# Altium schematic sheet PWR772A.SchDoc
size 431 x 279 mm; Date: Not shown in title block; ApprovedBy: Not shown in title block; CheckedBy: Not shown in title block; Author: Not shown in title block; CompanyName: Not shown in title block; Engineer: Not shown in title block; Organization: Not shown in title block; Address1: Not shown in title block; Address2: Not shown in title block; Address3: Not shown in title block; Address4: Not shown in title block; DocumentNumber: 1; Revision: Use project parameter SCH_Rev; SheetNumber: 1; SheetTotal: 2; PageSetup: Record=PageOptions¦CenterHorizontal=True¦CenterVertical=True¦PrintScale=0.62¦XCorrection=1.00¦YCorrection=1.00¦PrintKind=0¦BorderSize=5000000¦LeftOffset=0¦BottomOffset=0¦Orientation=2¦PaperLength=1000¦PaperWidth=1000¦Scale=100¦PaperSource=15¦PrintQuality=600¦MediaType=1¦DitherType=10¦PrintScaleMode=1¦PaperKind=Letter
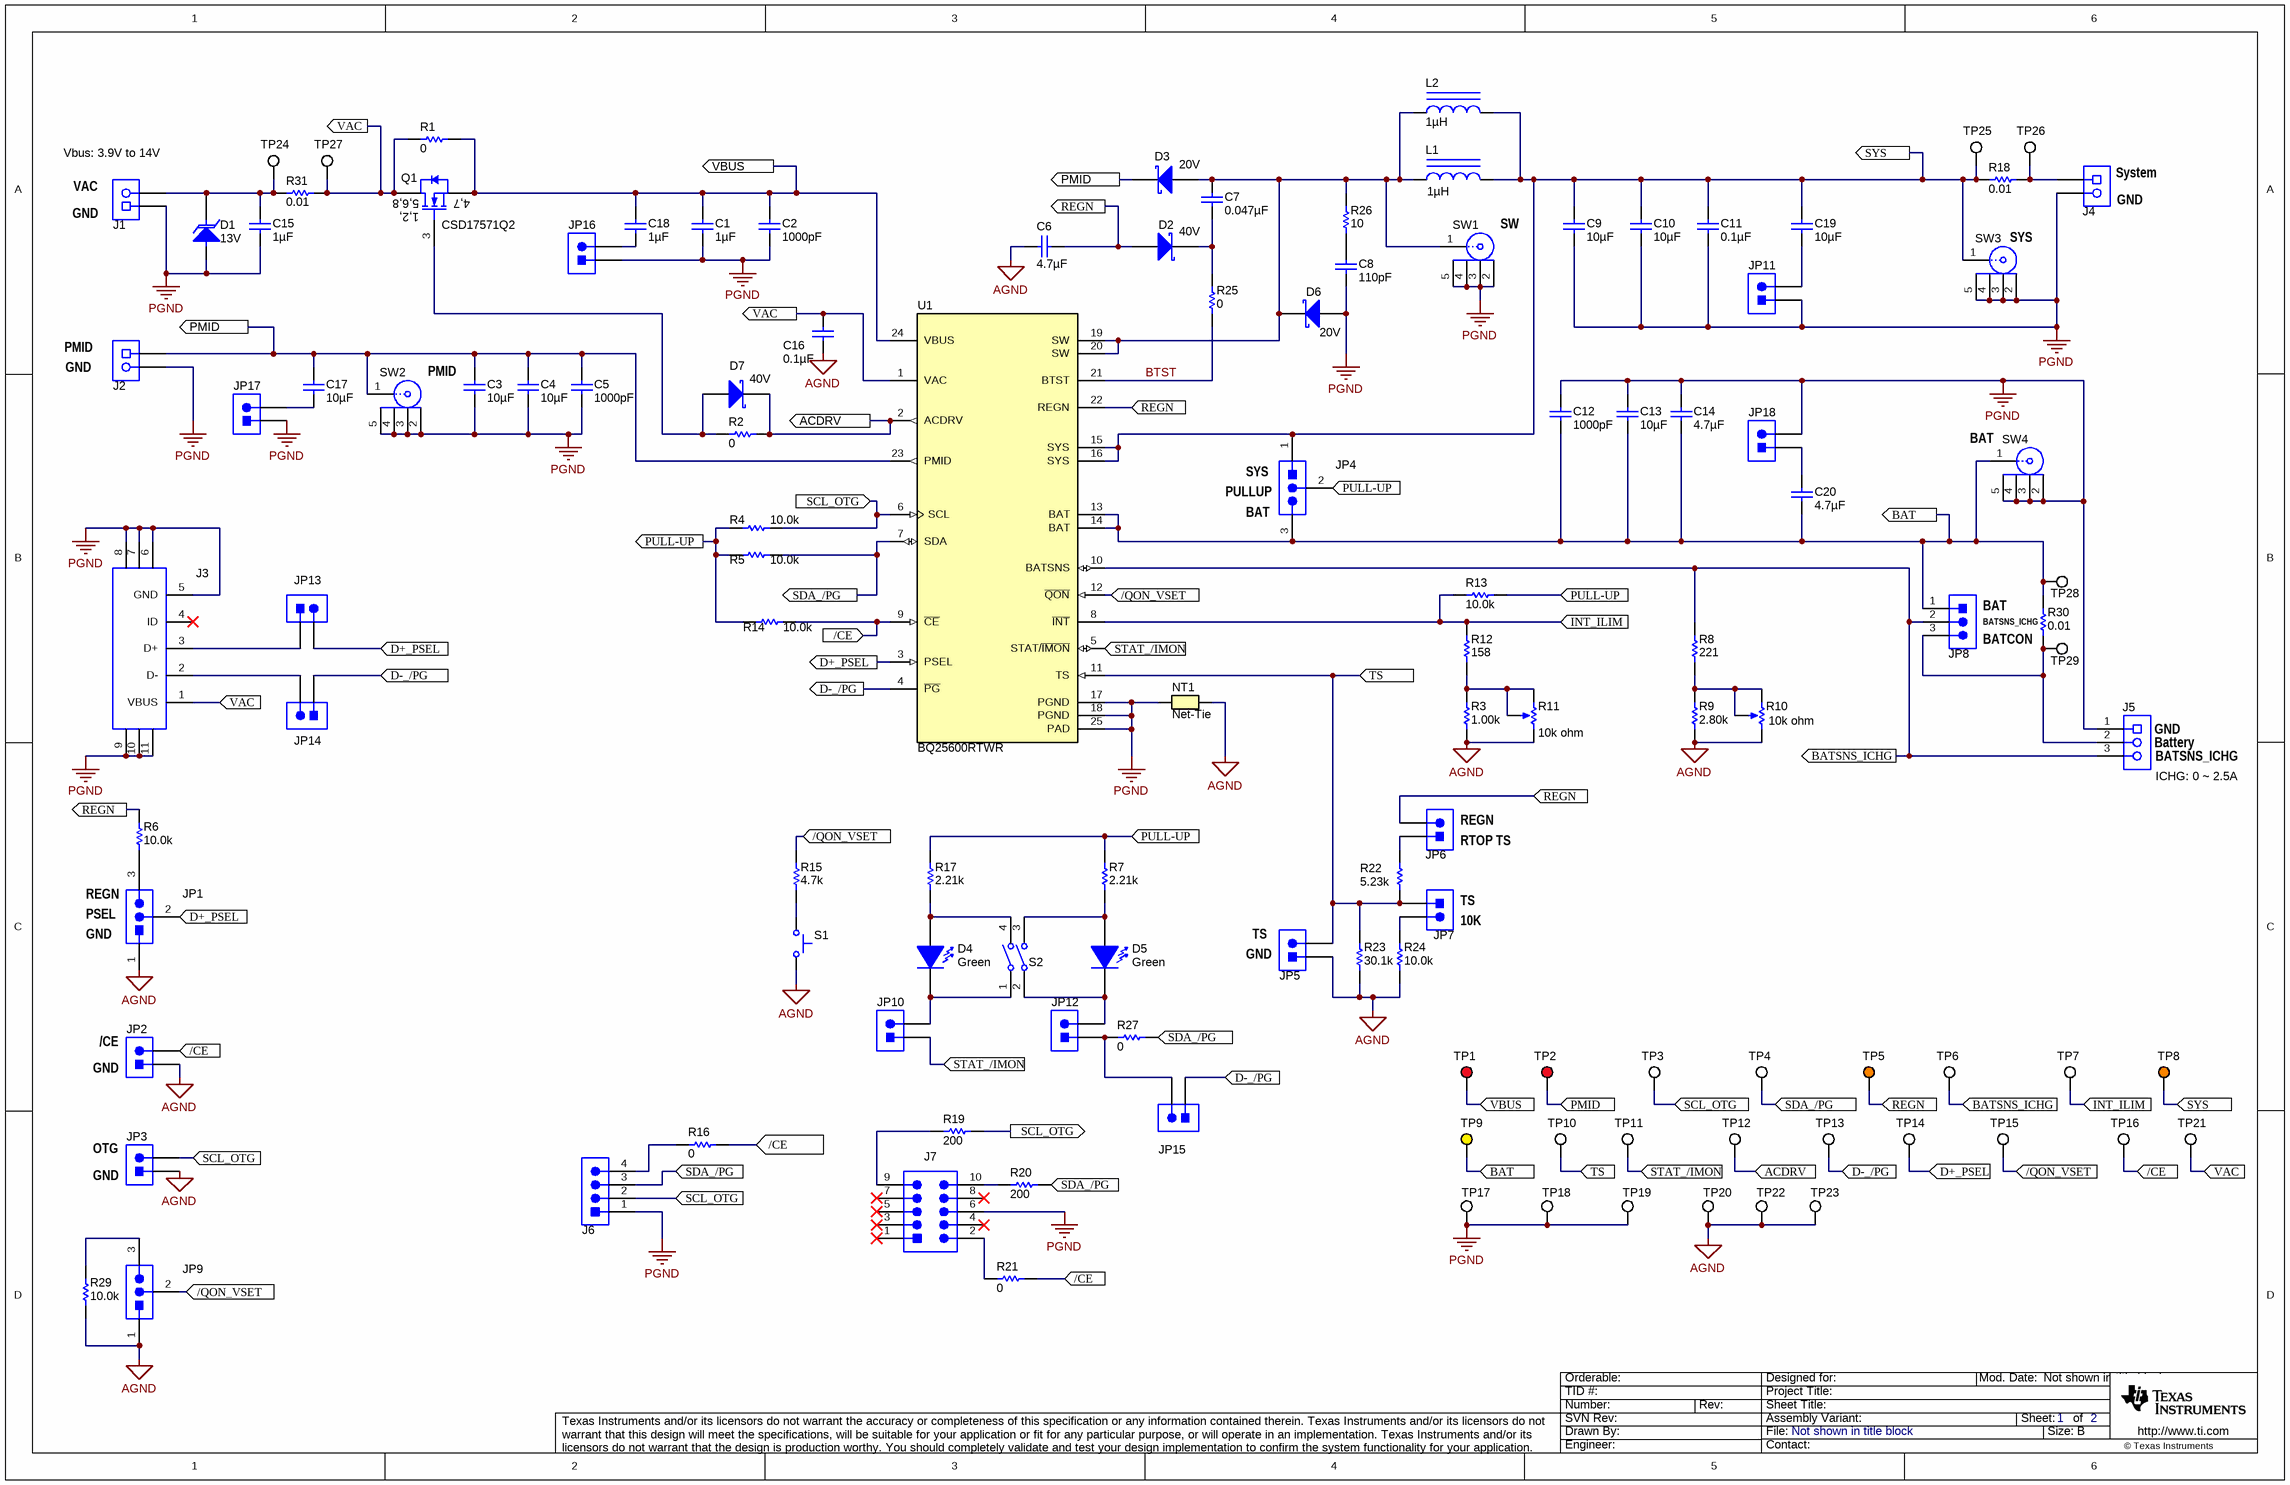
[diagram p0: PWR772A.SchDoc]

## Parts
C1  ValueDisplayed: 1µF  [0603L]  (hidden comment: GMK107BJ105KA-T)
C2  ValueDisplayed: 1000pF  [0402L]  (hidden comment: GRM1555C1H102JA01D)
C3  ValueDisplayed: 10µF  [0805L]  (hidden comment: GRM21BR61E106KA73L)
C4  ValueDisplayed: 10µF  [0805L]  (hidden comment: GRM21BC71E106KE11L)
C5  ValueDisplayed: 1000pF  [0402L]  (hidden comment: GRM1555C1H102JA01D)
C6  ValueDisplayed: 4.7µF  [0603L]  (hidden comment: GRM188R61C475KAAJ)
C7  ValueDisplayed: 0.047µF  [0402L]  (hidden comment: GRM155R71E473KA88D)
C8  ValueDisplayed: 110pF  [0402L]  (hidden comment: GRM1555C1E111JA01D)
C9  ValueDisplayed: 10µF  [0805L]  (hidden comment: GRM21BR71A106KE51L)
C10  ValueDisplayed: 10µF  [0805L]  (hidden comment: GRM21BR71A106KE51L)
C11  ValueDisplayed: 0.1µF  [0402L]  (hidden comment: C1005X7R1E104M050BB)
C12  ValueDisplayed: 1000pF  [0402L]  (hidden comment: GRM1555C1H102JA01D)
C13  ValueDisplayed: 10µF  [0805L]  (hidden comment: GRM21BR71A106KE51L)
C14  ValueDisplayed: 4.7µF  [0603L]  (hidden comment: GRM188R61C475KAAJ)
C15  ValueDisplayed: 1µF  [0805L]  (hidden comment: GRM219R71E105KA88D)
C16  ValueDisplayed: 0.1µF  [0402L]  (hidden comment: GRM155R71E104KE14D)
C17  ValueDisplayed: 10µF  [0805_HV]  (hidden comment: GRM21BR61E106KA73L)
C18  ValueDisplayed: 1µF  [0603]  (hidden comment: GMK107BJ105KA-T)
C19  ValueDisplayed: 10µF  [0805_HV]  (hidden comment: GRM21BR71A106KE51L)
C20  ValueDisplayed: 4.7µF  [0603]  (hidden comment: GRM188R61C475KAAJ)
D1  value 13V  [SOD-123W]  (hidden comment: PTVS13VS1UR,115)
D2  value 40V  [SOD-523]  (hidden comment: ZLLS350TA)
D3  value 20V  [152AD]  (hidden comment: NSR10F20NXT5G)
D4  value Green  [LED_LTST-C190]  (hidden comment: LTST-C190GKT)
D5  value Green  [LED_LTST-C190]  (hidden comment: LTST-C190GKT)
D6  value 20V  [152AD]  (hidden comment: NSR10F20NXT5G)
D7  value 40V  [SOD-523]  (hidden comment: ZLLS350TA)
J1  1727010  [PhoenixConact_1727010]  (value not drawn)
J2  1727010  [PhoenixConact_1727010]  (value not drawn)
J3  0473460001  [CONN_47346-0001]  (value not drawn)
J4  1727010  [PhoenixConact_1727010]  (value not drawn)
J5  1727023  [Phoenix_1727023]  (value not drawn)
J6  22-05-3041  [CONN_22-05-3041]  (value not drawn)
J7  N2510-6002-RB  [CONN_2510-6002]  (value not drawn)
JP1  PEC03SAAN  [CONN_PEC03SAAN]  (value not drawn)
JP2  PEC02SAAN  [CONN_PEC02SAAN]  (value not drawn)
JP3  PEC02SAAN  [CONN_PEC02SAAN]  (value not drawn)
JP4  PEC03SAAN  [CONN_PEC03SAAN]  (value not drawn)
JP5  PEC02SAAN  [CONN_PEC02SAAN]  (value not drawn)
JP6  PEC02SAAN  [CONN_PEC02SAAN]  (value not drawn)
JP7  PEC02SAAN  [CONN_PEC02SAAN]  (value not drawn)
JP8  PEC03SAAN  [CONN_PEC03SAAN]  (value not drawn)
JP9  PEC03SAAN  [CONN_PEC03SAAN]  (value not drawn)
JP10  PEC02SAAN  [CONN_PEC02SAAN]  (value not drawn)
JP11  PEC02SAAN  [CONN_PEC02SAAN]  (value not drawn)
JP12  PEC02SAAN  [CONN_PEC02SAAN]  (value not drawn)
JP13  PEC02SAAN  [CONN_PEC02SAAN]  (value not drawn)
JP14  PEC02SAAN  [CONN_PEC02SAAN]  (value not drawn)
JP15  PEC02SAAN  [CONN_PEC02SAAN]  (value not drawn)
JP16  PEC02SAAN  [CONN_PEC02SAAN]  (value not drawn)
JP17  PEC02SAAN  [CONN_PEC02SAAN]  (value not drawn)
JP18  PEC02SAAN  [CONN_PEC02SAAN]  (value not drawn)
L1  ValueDisplayed: 1µH  [WE-LHMI_4012]  (hidden comment: 74437321010)
L2  ValueDisplayed: 1µH  [MPIM252010F]  (hidden comment: MPIM252010F1R0M-LF)
NT1  Net-Tie  [Net-Tie_10milWide_30milLong]  (net tie, no BOM)
Q1  CSD17571Q2  [DQK0006C]
R1  ValueDisplayed: 0  [0603L]  (hidden comment: CRCW06030000Z0EA)
R2  ValueDisplayed: 0  [0402L]  (hidden comment: CRCW04020000Z0ED)
R3  ValueDisplayed: 1.00k  [0402]  (hidden comment: CRCW04021K00FKED)
R4  value 10.0k  [0402]  (hidden comment: CRCW04022K21FKED)
R5  value 10.0k  [0402]  (hidden comment: CRCW040210K0FKED)
R6  value 10.0k  [0402]  (hidden comment: CRCW040210K0FKED)
R7  value 2.21k  [0402]  (hidden comment: CRCW04022K21FKED)
R8  ValueDisplayed: 221  [0402]  (hidden comment: CRCW0402221RFKED)
R9  ValueDisplayed: 2.80k  [0402]  (hidden comment: CRCW04022K80FKED)
R10  value 10k ohm  [TRIM_3266W]  (hidden comment: 3266W-1-103LF)
R11  value 10k ohm  [TRIM_3266W]  (hidden comment: 3266W-1-103LF)
R12  ValueDisplayed: 158  [0402]  (hidden comment: CRCW0402158RFKED)
R13  value 10.0k  [0402]  (hidden comment: CRCW040210K0FKED)
R14  value 10.0k  [0402]  (hidden comment: CRCW040210K0FKED)
R15  value 4.7k  [0402]  (hidden comment: CRCW04024K70JNED)
R16  ValueDisplayed: 0  [0402]  (hidden comment: CRCW04020000Z0ED)
R17  value 2.21k  [0402]  (hidden comment: CRCW04022K21FKED)
R18  ValueDisplayed: 0.01  [2010]  (hidden comment: WSL2010R0100FEA18)
R19  value 200  [0402]  (hidden comment: CRCW0402200RFKED)
R20  value 200  [0402]  (hidden comment: CRCW0402200RFKED)
R21  ValueDisplayed: 0  [0402]  (hidden comment: CRCW04020000Z0ED)
R22  value 5.23k  [0402]  (hidden comment: CRCW04025K23FKED)
R23  value 30.1k  [0402]  (hidden comment: CRCW040230K1FKED)
R24  value 10.0k  [0402]  (hidden comment: CRCW040210K0FKED)
R25  ValueDisplayed: 0  [0402L]  (hidden comment: CRCW04020000Z0ED)
R26  ValueDisplayed: 10  [0402L]  (hidden comment: CRCW040210R0JNED)
R27  ValueDisplayed: 0  [0402L]  (hidden comment: CRCW04020000Z0ED)
R29  value 10.0k  [0402]  (hidden comment: CRCW040210K0FKED)
R30  ValueDisplayed: 0.01  [2010]  (hidden comment: WSL2010R0100FEA18)
R31  ValueDisplayed: 0.01  [2010]  (hidden comment: WSL2010R0100FEA18)
S1  KSR221GLFS  [KSR]  (value not drawn)
S2  218-2LPST  [SW_218-2LP]  (value not drawn)
SW1  SW  [Tek_131-5031-00]  (value not drawn)
SW2  PMID  [Tek_131-5031-00]  (value not drawn)
SW3  SYS  [Tek_131-5031-00]  (value not drawn)
SW4  BAT  [Tek_131-5031-00]  (value not drawn)
TP1  5000  [Keystone5000]  (value not drawn)
TP2  5000  [Keystone5000]  (value not drawn)
TP3  5002  [Keystone5002]  (value not drawn)
TP4  5002  [Keystone5002]  (value not drawn)
TP5  5003  [Keystone5003]  (value not drawn)
TP6  5002  [Keystone5002]  (value not drawn)
TP7  5002  [Keystone5002]  (value not drawn)
TP8  5003  [Keystone5003]  (value not drawn)
TP9  5004  [Keystone5004]  (value not drawn)
TP10  5002  [Keystone5002]  (value not drawn)
TP11  5002  [Keystone5002]  (value not drawn)
TP12  5002  [Keystone5002]  (value not drawn)
TP13  5002  [Keystone5002]  (value not drawn)
TP14  5002  [Keystone5002]  (value not drawn)
TP15  5002  [Keystone5002]  (value not drawn)
TP16  5002  [Keystone5002]  (value not drawn)
TP17  5016  [Testpoint_Keystone_Compact]  (value not drawn)
TP18  5016  [Testpoint_Keystone_Compact]  (value not drawn)
TP19  5016  [Testpoint_Keystone_Compact]  (value not drawn)
TP20  5016  [Testpoint_Keystone_Compact]  (value not drawn)
TP21  5002  [Keystone5002]  (value not drawn)
TP22  5016  [Testpoint_Keystone_Compact]  (value not drawn)
TP23  5016  [Testpoint_Keystone_Compact]  (value not drawn)
TP24  5002  [Keystone5002]  (value not drawn)
TP25  5002  [Keystone5002]  (value not drawn)
TP26  5002  [Keystone5002]  (value not drawn)
TP27  5002  [Keystone5002]  (value not drawn)
TP28  5002  [Keystone5002]  (value not drawn)
TP29  5002  [Keystone5002]  (value not drawn)
U1  BQ25600RTWR  [RTW0024H]

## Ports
/CE, /CE (in), /QON_VSET, ACDRV, BAT, BATSNS_ICHG, D+_PSEL, D-_/PG, INT_ILIM, PMID, PULL-UP, REGN, SCL_OTG, SDA_/PG, STAT_/IMON, SYS, TS, VAC, VBUS

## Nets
AGND: C6.2 C16.2 JP1.1 JP2.1 JP3.1 JP5.1 JP9.1 NT1.2 R3.1 R9.1 R10.3(CW) R11.3(CW) R23.1 R24.1 R29.1 S1.2 TP20.1 TP22.1 TP23.1
PGND: C1.2 C2.2 C3.2 C4.2 C5.2 C8.2 C9.2 C10.2 C11.2 C12.1 C13.1 C14.1 C15.2 D1.2(A) D6.2(A) J1.1 J2.2 J3.5(GND) J3.6 J3.7 J3.8 J3.9 J3.10 J3.11 J4.2 J5.1 J6.1 J7.6 JP11.1 JP16.1 JP17.1 JP18.2 NT1.1 SW1.2 SW1.3 SW1.4 SW1.5 SW2.2 SW2.3 SW2.4 SW2.5 SW3.2 SW3.3 SW3.4 SW3.5 SW4.2 SW4.3 SW4.4 SW4.5 TP17.1 TP18.1 TP19.1 U1.17(PGND) U1.18(PGND) U1.25(PAD)
/CE: JP2.2 R14.2 R16.2 R21.2 TP16.1 U1.9(~{CE}) ; port /CE
/QON_VSET: JP9.2 R15.2 TP15.1 U1.12(~{QON}) ; port /QON_VSET
ACDRV: D7.1(K) R2.1 TP12.1 U1.2(ACDRV) ; port ACDRV
BAT: C12.2 C13.2 C14.2 C20.2 JP4.3 JP8.1 R30.1 SW4.1 TP9.1 TP28.1 U1.13(BAT) U1.14(BAT) ; port BAT
BATSNS_ICHG: J5.3 JP8.2 R8.2 TP6.1 U1.10(BATSNS) ; port BATSNS_ICHG
BTST: R25.2 U1.21(BTST)
D+_PSEL: JP1.2 JP13.2 TP14.1 U1.3(PSEL) ; port D+_PSEL
D-_/PG: JP14.1 JP15.1 TP13.1 U1.4(~{PG}) ; port D-_/PG
INT_ILIM: R12.2 R13.2 TP7.1 U1.8(~{INT}) ; port INT_ILIM
PMID: C3.1 C4.1 C5.1 C17.1 D3.1(K) J2.1 SW2.1 TP2.1 U1.23(PMID) ; port PMID
PULL-UP: JP4.2 R4.1 R5.1 R7.2 R13.1 R14.1 R17.2 ; port PULL-UP
REGN: C6.1 D2.2(A) JP6.2 R6.2 TP5.1 U1.22(REGN) ; port REGN
SCL_OTG: J6.2 JP3.2 R4.2 R19.1 TP3.1 U1.6(SCL) ; port SCL_OTG
SDA_/PG: J6.3 R5.2 R20.2 R27.1 TP4.1 U1.7(SDA) ; port SDA_/PG
STAT_/IMON: JP10.1 TP11.1 U1.5(STAT/~{IMON}) ; port STAT_/IMON
SYS: C9.1 C10.1 C11.1 C19.1 JP4.1 L1.2 L2.2 R18.1 SW3.1 TP8.1 TP25.1 U1.15(SYS) U1.16(SYS) ; port SYS
TS: JP5.2 JP7.1 R22.1 R23.2 TP10.1 U1.11(TS) ; port TS
VAC: C16.1 J3.1(VBUS) Q1.1(D) Q1.2(D) Q1.5(D) Q1.6(D) Q1.8(D) R1.1 R31.2 TP21.1 TP27.1 U1.1(VAC) ; port VAC
VBUS: C1.1 C2.1 C18.1 Q1.4(S) Q1.7(S) R1.2 TP1.1 U1.24(VBUS) ; port VBUS
NetC7_1: C7.1 D3.2(A) D6.1(K) L1.1 L2.1 R26.2 SW1.1 U1.19(SW) U1.20(SW)
NetC7_2: C7.2 D2.1(K) R25.1
NetC8_1: C8.1 R26.1
NetC15_1: C15.1 D1.1(K) J1.2 R31.1 TP24.1
NetC17_2: C17.2 JP17.2
NetC18_2: C18.2 JP16.2
NetC19_2: C19.2 JP11.2
NetC20_1: C20.1 JP18.1
NetD4_1: D4.1(A) R17.1 S2.4
NetD4_2: D4.2(K) JP10.2 S2.1
NetD5_1: D5.1(A) R7.1 S2.3
NetD5_2: D5.2(K) JP12.2 S2.2
NetD7_2: D7.2(A) Q1.3(G) R2.2
NetJ3_2: J3.2(D-) JP14.2
NetJ3_3: J3.3(D+) JP13.1
NetJ4_1: J4.1 R18.2 TP26.1
NetJ5_2: J5.2 JP8.3 R30.2 TP29.1
NetJ6_4: J6.4 R16.1
NetJ7_2: J7.2 R21.1
NetJ7_9: J7.9 R19.2
NetJ7_10: J7.10 R20.1
NetJP1_3: JP1.3 R6.1
NetJP6_1: JP6.1 R22.2
NetJP7_2: JP7.2 R24.2
NetJP9_3: JP9.3 R29.2
NetJP12_1: JP12.1 JP15.2 R27.2
NetR3_2: R3.2 R11.1(CCW) R11.2(WIPER) R12.1
NetR8_1: R8.1 R9.2 R10.1(CCW) R10.2(WIPER)
NetR15_1: R15.1 S1.1

Not connected (* = marked no-connect by the designer): J3 4(ID)*; J7 1* 3* 4* 5* 7* 8*

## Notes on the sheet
- (near J1) Vbus: 3.9V to 14V
- (near J4) System
- (near J1) VAC
- (near J1) GND
- (near SW1) SW
- (near J4) GND
- (near SW3) SYS
- (near J2) PMID
- (near J2) GND
- PMID
- (near JP4) PULLUP
- (near JP4) SYS
- (near SW4) BAT
- (near JP4) BAT
- (near R30) BATSNS_ICHG
- BAT
- (near R30) BATCON
- (near J5) GND
- (near J5) Battery
- (near J5) BATSNS_ICHG
- (near JP6) REGN
- (near J5) ICHG: 0 ~ 2.5A
- (near JP1) REGN
- (near JP6) RTOP TS
- (near JP1) PSEL
- (near JP1) GND
- (near JP5) GND
- (near JP5) TS
- (near JP7) 10K
- (near JP7) TS
- (near JP2) GND
- (near JP2) /CE
- (near JP3) OTG
- (near JP3) GND

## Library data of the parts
C1 = GMK107BJ105KA-T: CAP, CERM, 1 µF, 35 V, +/- 10%, X5R, 0603; Manufacturer: Taiyo Yuden; Polarized: N; CompType: Capacitor; Value: 1uF; U/M: EA; Cap_F: 0.000001; Tolerance_%: 10; Value1: Unknown; VDC_V: 35; Value2: 35V; TaMin_C: -55; TaMax_C: 85; Cap_Case: 0603; AEC Category: Q200
C2 C5 C12 = GRM1555C1H102JA01D: CAP, CERM, 1000 pF, 50 V, +/- 5%, C0G/NP0, 0402; Manufacturer: MuRata; Polarized: N; CompType: Capacitor; Value: 1000pF; U/M: EA; Cap_F: 0.000000001; Tolerance_%: 5; Value1: Unknown; VDC_V: 50; Value2: 50V; TaMin_C: -55; TaMax_C: 125; Cap_Case: 0402; AEC Category: Q200; SizeArea_mm2: 0.5; SizeAreaWB_mm2: 3; SizeX_mm: 1; SizeZ_mm: 0.6
C3 C17 = GRM21BR61E106KA73L: CAP, CERM, 10 µF, 25 V, +/- 10%, X5R, 0805; Manufacturer: MuRata; Polarized: N; CompType: Capacitor; Value: 10uF; U/M: EA; Cap_F: 0.00001; Tolerance_%: 10; Value1: Unknown; VDC_V: 25; Value2: 25V; TaMin_C: -55; TaMax_C: 85; Cap_Case: 0805; AEC Category: Q200
C4 = GRM21BC71E106KE11L: CAP, CERM, 10 µF, 25 V, +/- 10%, X7S, 0805; Manufacturer: MuRata; Polarized: N; CompType: Capacitor; Value: 10uF; U/M: EA; Cap_F: 0.00001; Tolerance_%: 10; Value1: Unknown; VDC_V: 25; Value2: 25V; TaMin_C: -55; TaMax_C: 125; Cap_Case: 0805; AEC Category: Q200
C6 C14 = GRM188R61C475KAAJ: CAP, CERM, 4.7 µF, 16 V, +/- 10%, X5R, 0603; Manufacturer: MuRata; Polarized: N; CompType: Capacitor; Value: 4.7uF; U/M: EA; Cap_F: 0.0000047; Tolerance_%: 10; Value1: Unknown; VDC_V: 16; Value2: 16V; TaMin_C: -55; TaMax_C: 85; Cap_Case: 0603; AEC Category: Q200
C7 = GRM155R71E473KA88D: CAP, CERM, 0.047 µF, 25 V, +/- 10%, X7R, 0402; Manufacturer: MuRata; Polarized: N; CompType: Capacitor; Value: 0.047uF; U/M: EA; Cap_F: 0.000000047; Tolerance_%: 10; Value1: Unknown; VDC_V: 25; Value2: 25V; TaMin_C: -55; TaMax_C: 125; Cap_Case: 0402; AEC Category: Q200
C8 = GRM1555C1E111JA01D: CAP, CERM, 110 pF, 25 V, +/- 5%, C0G/NP0, 0402; Manufacturer: MuRata; Polarized: N; CompType: Capacitor; Value: 110pF; U/M: EA; Cap_F: 0.00000000011; Tolerance_%: 5; Value1: Unknown; VDC_V: 25; Value2: 25V; TaMin_C: -55; TaMax_C: 125; Cap_Case: 0402; AEC Category: Q200
C9 C10 C19 = GRM21BR71A106KE51L: CAP, CERM, 10 µF, 10 V, +/- 10%, X7R, 0805; Manufacturer: MuRata; Polarized: N; CompType: Capacitor; Value: 10uF; U/M: EA; Cap_F: 0.00001; Tolerance_%: 10; ESR_ohm: 0.003; Value1: 0.003 ohm; Value2: 10V; TaMin_C: -55; TaMax_C: 125; Cap_Case: 0805; AEC Category: Q200
C11 = C1005X7R1E104M050BB: CAP, CERM, 0.1 µF, 25 V, +/- 20%, X7R, 0402; Manufacturer: TDK; Polarized: N; CompType: Capacitor; Value: 0.1uF; U/M: EA; Cap_F: 0.0000001; Tolerance_%: 20; Value1: Unknown; VDC_V: 25; Value2: 25V; TaMin_C: -55; TaMax_C: 125; Cap_Case: 0402; AEC Category: Q200
C13 = GRM21BR71A106KE51L: CAP, CERM, 10 µF, 10 V, +/- 10%, X7R, 0805; Manufacturer: MuRata; Polarized: N; CompType: Capacitor; Value: 10uF; U/M: EA; Cap_F: 0.00001; Tolerance_%: 10; ESR_ohm: 0.003; Value1: 0.003 ohm; Value2: 10V; TaMin_C: -55; TaMax_C: 125; Cap_Case: 0805; AEC Category: Q200; SizeArea_mm2: 2.5; SizeAreaWB_mm2: 6.75; SizeX_mm: 2; SizeY_mm: 1.25; SizeZ_mm: 1.45
C15 = GRM219R71E105KA88D: CAP, CERM, 1 µF, 25 V, +/- 10%, X7R, 0805; Manufacturer: MuRata; Polarized: N; CompType: Capacitor; Value: 1uF; U/M: EA; Cap_F: 0.000001; Tolerance_%: 10; Value1: Unknown; VDC_V: 25; Value2: 25V; TaMin_C: -55; TaMax_C: 125; Cap_Case: 0805; AEC Category: Q200
C16 = GRM155R71E104KE14D: CAP, CERM, 0.1 µF, 25 V, +/- 10%, X7R, 0402; Manufacturer: MuRata; Polarized: N; CompType: Capacitor; Value: 0.1uF; U/M: EA; Cap_F: 0.0000001; Tolerance_%: 10; Value1: Unknown; VDC_V: 25; Value2: 25V; TaMin_C: -55; TaMax_C: 125; Cap_Case: 0402; AEC Category: Q200
C18 = GMK107BJ105KA-T: CAP, CERM, 1 µF, 35 V, +/- 10%, X5R, 0603; Manufacturer: Taiyo Yuden; Polarized: N; CompType: Capacitor; Value: 1uF; U/M: EA; Cap_F: 0.000001; Tolerance_%: 10; Value1: Unknown; VDC_V: 35; Value2: 35V; TaMin_C: -55; TaMax_C: 85; AEC Category: Q200
C20 = GRM188R61C475KAAJ: CAP, CERM, 4.7 µF, 16 V, +/- 10%, X5R, 0603; Manufacturer: MuRata; Polarized: N; CompType: Capacitor; Value: 4.7uF; U/M: EA; Cap_F: 0.0000047; Tolerance_%: 10; Value1: Unknown; VDC_V: 16; Value2: 16V; TaMin_C: -55; TaMax_C: 85; AEC Category: Q200
D1 = PTVS13VS1UR,115: Diode, TVS, Uni, 13 V,  W, SOD-123W; Manufacturer: NXP Semiconductor; U/M: EA; Power_W: 400; Vr_V: 13; Value1: 400W; RJA_CperW: 220; AEC Category: Q101
D2 D7 = ZLLS350TA: Diode, Schottky, 40 V, 0.38 A, SOD-523; Manufacturer: Diodes Inc.; U/M: EA; Vf_V: 0.79; Value1: 0.38A; Value2: 0.79V; Io_A: 0.38; Vr_V: 40; AEC Category: Q101
D3 D6 = NSR10F20NXT5G: Diode, Schottky, 20 V, 1 A, 152AD; Manufacturer: ON Semiconductor; U/M: EA; Vf_V: 0.45; Value1: 1A; Value2: 0.45V; Io_A: 1; Vr_V: 20; TJmax_C: 150; AEC Category: Q101
D4 D5 = LTST-C190GKT: LED, Green, SMD; Manufacturer: Lite-On; Vf_V: 2.1; Value2: 2.1V; Io_A: 0.02; Power_TotalModule: 0.1; Value1: 0.1W; U/M: EA
J1 J2 J4 = 1727010: Conn Term Block, 2POS, 3.81mm, TH; Manufacturer: Phoenix Contact; SymbolCreator: a0412235; CompType: Terminal Block
J3 = 0473460001: Connector, Receptacle, Micro-USB Type B, R/A, Bottom Mount SMT; Manufacturer: Molex; SymbolCreator: a0411947
J5 = 1727023: Terminal Block Receptacle, 3x1, 3.81mm, R/A, TH; Manufacturer: Phoenix Contact; SymbolCreator: a0412235
J6 = 22-05-3041: Header (friction lock), 100mil, 4x1, R/A, TH; Manufacturer: Molex; SymbolCreator: a0412235
J7 = N2510-6002-RB: Header (shrouded), 100mil, 5x2, High-Temperature, Gold, TH; Manufacturer: 3M; SymbolCreator: a0412235
JP1 JP4 JP8 JP9 = PEC03SAAN: Header, 100mil, 3x1, Tin, TH; Manufacturer: Sullins Connector Solutions; SymbolCreator: a0799628; Pitch_mm: 2.54; Gender: Male; Shrouded: N; Row_Count: 1; Current_A: 3; Voltage_V: 1800; Cert_UL: Y
JP2 JP3 JP5-JP7 JP10-JP18 = PEC02SAAN: Header, 100mil, 2x1, Tin, TH; Manufacturer: Sullins Connector Solutions; SymbolCreator: a0412235; Pitch_mm: 2.54; Gender: Male; Shrouded: N; Row_Count: 1; Current_A: 3; Voltage_V: 1800; Cert_UL: Y
L1 = 74437321010: Inductor, Wirewound, 1 µH, 4 A, 0.041 ohm, SMD; Manufacturer: Wurth Elektronik; Value: 1uH; Ind_H: 1.0E-6; Imax_A: 4; Irms: 4A @ 40C rise; Isat: 7.5A @ 20% inductance drop; DCR_ohm: 0.041; Value2: 4A; AEC Category: Q200; AEC Qualified: N
L2 = MPIM252010F1R0M-LF: Inductor, 1 µH, 3.2 A, 0.028 ohm, SMD; Manufacturer: Microgate; Value: 1uH; Ind_H: 1.0E-6; Imax_A: 3.2; Irms: 3.2A @ 40C rise; Isat: 4A @ 30% inductance drop; DCR_ohm: 0.028; Value2: 3.2A; SizeAreaWB_mm2: 10.5; SizeArea_mm2: 5; SizeX_mm: 2.5; SizeY_mm: 2; SizeZ_mm: 1; AEC Category: Q200; AEC Qualified: N
NT1 = Net-Tie: Single point connection between nets.; SymbolCreator: codlsc
Q1 = CSD17571Q2: MOSFET, N-CH, 30 V, 22 A, DQK0006C (WSON-6); Manufacturer: Texas Instruments; Alternate Manufacturer: None; U/M: EA; ChType: N; Value: 30V; VdsMax_V: 30; Value1: 0.029 ohm; Rdson45_ohm: 0.029; Value2: 2.4 nC; QgTyp_nC: 2.4; Vgs_V: 20; IdsMax_A: 22; AEC Category: Q101; SizeAreaWB_mm2: 9; SizeArea_mm2: 4; SizeX_mm: 2; SizeZ_mm: 0.8
R1 = CRCW06030000Z0EA: RES, 0, 5%, 0.1 W, 0603; Manufacturer: Vishay-Dale; CompType: Resistor; Value: 0; Value_Code: 0000; Tolerance_%: 5; Power_W: 0.1; Value2: 0.1W; VDC_V: 75; TempCo: 200 ppm/C; EIA_Code: E24; U/M: EA; AEC Category: Q200
R2 R16 R21 R27 = CRCW04020000Z0ED: RES, 0, 5%, 0.063 W, 0402; Manufacturer: Vishay-Dale; CompType: Resistor; Value: 0; Value_Code: 0000; Tolerance_%: 5; Power_W: 0.063; Value2: 0.063W; VDC_V: 50; TempCo: 200 ppm/C; EIA_Code: E24; U/M: EA; AEC Category: Q200
R3 = CRCW04021K00FKED: RES, 1.00 k, 1%, 0.063 W, 0402; Manufacturer: Vishay-Dale; CompType: Resistor; Value: 1.00k; Res_ohm: 1000; Value_Code: 1k00; Tolerance_%: 1; Power_W: 0.063; Value2: 0.063W; VDC_V: 50; TempCo: 100 ppm/C; EIA_Code: E96; U/M: EA; AEC Category: Q200
R4-R6 R13 R14 R24 R29 = CRCW040210K0FKED: RES, 10.0 k, 1%, 0.063 W, 0402; Manufacturer: Vishay-Dale; CompType: Resistor; Res_ohm: 10000; Value_Code: 10k0; Tolerance_%: 1; Power_W: 0.063; Value2: 0.063W; VDC_V: 50; TempCo: 100 ppm/C; EIA_Code: E96; U/M: EA; AEC Category: Q200
R7 R17 = CRCW04022K21FKED: RES, 2.21 k, 1%, 0.063 W, 0402; Manufacturer: Vishay-Dale; CompType: Resistor; Res_ohm: 2210; Value_Code: 2k21; Tolerance_%: 1; Power_W: 0.063; Value2: 0.063W; VDC_V: 50; TempCo: 100 ppm/C; EIA_Code: E96; U/M: EA; AEC Category: Q200
R8 = CRCW0402221RFKED: RES, 221, 1%, 0.063 W, 0402; Manufacturer: Vishay-Dale; CompType: Resistor; Value: 221; Value_Code: 221R; Tolerance_%: 1; Power_W: 0.063; Value2: 0.063W; VDC_V: 50; TempCo: 100 ppm/C; EIA_Code: E96; U/M: EA; AEC Category: Q200
R9 = CRCW04022K80FKED: RES, 2.80 k, 1%, 0.063 W, 0402; Manufacturer: Vishay-Dale; CompType: Resistor; Value: 2.80k; Res_ohm: 2800; Value_Code: 2k80; Tolerance_%: 1; Power_W: 0.063; Value2: 0.063W; VDC_V: 50; TempCo: 100 ppm/C; EIA_Code: E96; U/M: EA; AEC Category: Q200
R10 R11 = 3266W-1-103LF: Trimmer, 10k ohm, 0.25W, TH; Manufacturer: Bourns; Sim Note: Enter the Resistance value and the set point into parameter fields.; SymbolCreator: a0412235
R12 = CRCW0402158RFKED: RES, 158, 1%, 0.063 W, 0402; Manufacturer: Vishay-Dale; CompType: Resistor; Value: 158; Value_Code: 158R; Tolerance_%: 1; Power_W: 0.063; Value2: 0.063W; VDC_V: 50; TempCo: 100 ppm/C; EIA_Code: E96; U/M: EA; AEC Category: Q200
R15 = CRCW04024K70JNED: RES, 4.7 k, 5%, 0.063 W, 0402; Manufacturer: Vishay-Dale; CompType: Resistor; Res_ohm: 4700; Value_Code: 4k70; Tolerance_%: 5; Power_W: 0.063; Value2: 0.063W; VDC_V: 50; TempCo: 200 ppm/C; EIA_Code: E24; U/M: EA; AEC Category: Q200
R18 R30 R31 = WSL2010R0100FEA18: RES, 0.01, 1%, 1 W, 2010; Manufacturer: Vishay-Dale; CompType: Resistor; Value: 0.01; Value_Code: R010; Tolerance_%: 1; Value2: 1W; TempCo: 75 ppm/C; EIA_Code: E96; U/M: EA; AEC Category: Q200
R19 R20 = CRCW0402200RFKED: RES, 200, 1%, 0.063 W, 0402; Manufacturer: Vishay-Dale; CompType: Resistor; Value_Code: 200R; Tolerance_%: 1; Power_W: 0.063; Value2: 0.063W; VDC_V: 50; TempCo: 100 ppm/C; EIA_Code: E96; U/M: EA; AEC Category: Q200
R22 = CRCW04025K23FKED: RES, 5.23 k, 1%, 0.063 W, 0402; Manufacturer: Vishay-Dale; CompType: Resistor; Res_ohm: 5230; Value_Code: 5k23; Tolerance_%: 1; Power_W: 0.063; Value2: 0.063W; VDC_V: 50; TempCo: 100 ppm/C; EIA_Code: E96; U/M: EA; AEC Category: Q200
R23 = CRCW040230K1FKED: RES, 30.1 k, 1%, 0.063 W, 0402; Manufacturer: Vishay-Dale; CompType: Resistor; Res_ohm: 30100; Value_Code: 30k1; Tolerance_%: 1; Power_W: 0.063; Value2: 0.063W; VDC_V: 50; TempCo: 100 ppm/C; EIA_Code: E96; U/M: EA; AEC Category: Q200
R25 = CRCW04020000Z0ED: RES, 0, 5%, 0.063 W, 0402; Manufacturer: Vishay-Dale; CompType: Resistor; Value_Code: 0000; Tolerance_%: 5; Power_W: 0.063; Value2: 0.063W; VDC_V: 50; TempCo: 200 ppm/C; EIA_Code: E24; U/M: EA; Value: 0; AEC Category: Q200
R26 = CRCW040210R0JNED: RES, 10, 5%, 0.063 W, 0402; Manufacturer: Vishay-Dale; CompType: Resistor; Value: 10; Value_Code: 10R0; Tolerance_%: 5; Power_W: 0.063; Value2: 0.063W; VDC_V: 50; TempCo: 200 ppm/C; EIA_Code: E24; U/M: EA; AEC Category: Q200
S1 = KSR221GLFS: Switch, Normally open, 2.3N force, 200k operations, SMD; Manufacturer: C&K Components; Circuit: SPST Switch; VDC_V: 32; SwitchFunction: Off-Mom; PositionCount: 1; CurrentRating_mA: 1001
S2 = 218-2LPST: Switch, SPST, 2 Pos, 25mA, 24VDC, SMD; Manufacturer: CTS Electrocomponents; SymbolCreator: Altium; VDC_V: 24; SwitchFunction: Off-On; PositionCount: 2; CurrentRating_mA: 25
SW1-SW4 = 131-5031-00: Compact Probe Tip Circuit Board Test Points, TH, 25 per; Manufacturer: Tektronix
TP1 TP2 = 5000: Test Point, Miniature, Red, TH; Manufacturer: Keystone; CompType: Test Point Loop; ContactFinish: Silver
TP3 TP4 TP6 TP7 TP10-TP16 TP21 TP24-TP29 = 5002: Test Point, Miniature, White, TH; Manufacturer: Keystone; CompType: Test Point Loop; ContactFinish: Silver
TP5 TP8 = 5003: Test Point, Miniature, Orange, TH; Manufacturer: Keystone; CompType: Test Point Loop; ContactFinish: Silver
TP9 = 5004: Test Point, Miniature, Yellow, TH; Manufacturer: Keystone; CompType: Test Point Loop; ContactFinish: Silver
TP17-TP20 TP22 TP23 = 5016: Test Point, Compact, SMT; Manufacturer: Keystone; CompType: Test Point Loop
U1 = BQ25600RTWR: BQ25600RTW, RTW0024H (WQFN-24); Alternate PartNumber: BQ25600RTWT; Manufacturer: Texas Instruments; SymbolCreator: Altium; SizeArea_mm2: 16; SizeAreaWB_mm2: 25; SizeX_mm: 4; SizeZ_mm: 0.8; CompType: IC; U/M: EA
